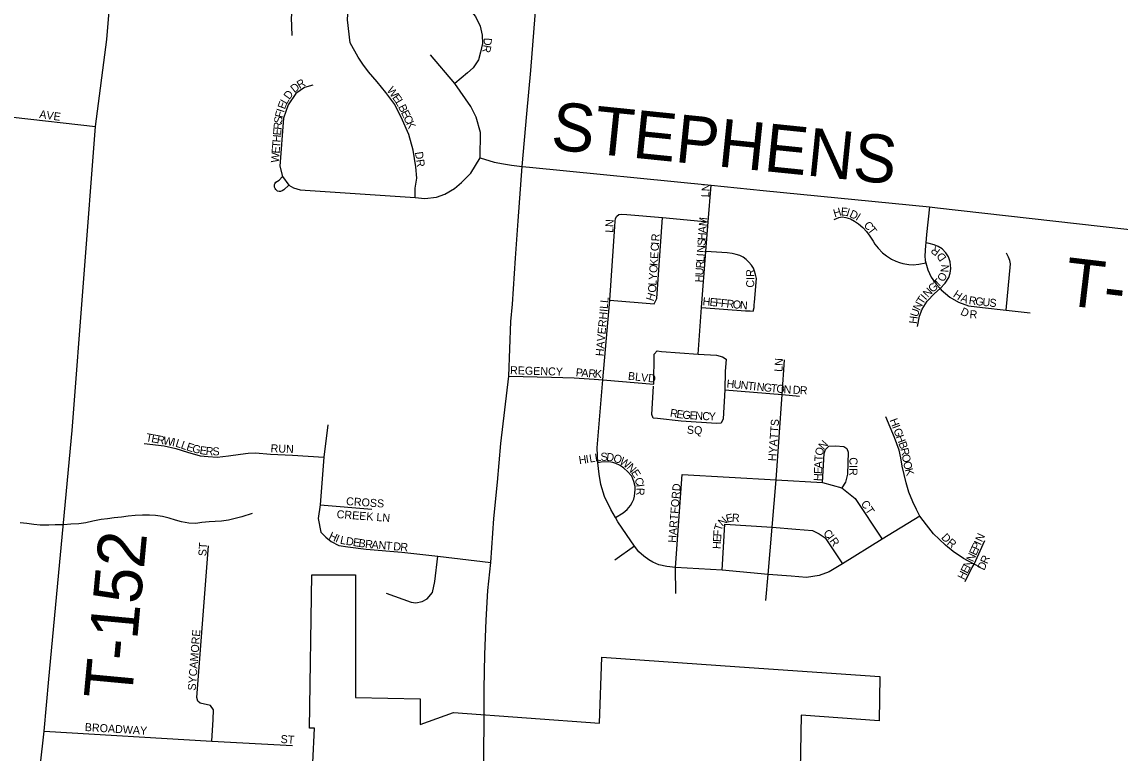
# Model space of a CAD drawing. Extents: x 0 to 1064, y 0 to 440.
# Drawn here: x 220.01 to 240.8, y 110.2 to 124.05 of the extents above; entities that cross this region are included whole.
import ezdxf

# ---------------------------------------------------------------- set-up
doc = ezdxf.new("R2010")
doc.units = 0
for name, color, linetype in [('GM_X_Corporation', 7, 'Continuous'), ('GM_X_Minor_River', 7, 'Continuous'), ('GM_X_State_Route', 7, 'Continuous'), ('GM_X_Township_Road', 7, 'Continuous'), ('GM_X_Township_Road_Text', 7, 'Continuous'), ('GM_X_Township_Subdivision', 7, 'Continuous'), ('GM_X_Township_Subdivision_Text', 7, 'Continuous')]:
    doc.layers.add(name, color=color, linetype=linetype)

msp = doc.modelspace()

# ---------------------------------------------------------------- linework, layer by layer
at = {"layer": 'GM_X_Corporation'}
msp.add_lwpolyline([(225.519, 110.017), (225.548, 110.674), (225.453, 110.674), (225.498, 113.577), (226.325, 113.577), (226.326, 111.25), (227.548, 111.229), (227.548, 110.742), (228.179, 110.967), (230.947, 110.769), (230.991, 112.016), (233.597, 111.834), (236.254, 111.649), (236.239, 110.812), (234.761, 110.916), (234.719, 108.501)], dxfattribs=at)
at = {"layer": 'GM_X_Minor_River'}
msp.add_lwpolyline([(224.371, 114.74), (224.175, 114.677), (224.047, 114.642), (223.925, 114.614), (223.791, 114.592), (223.669, 114.587), (223.554, 114.583), (223.42, 114.567), (223.304, 114.551), (223.17, 114.553), (223.031, 114.579), (222.916, 114.612), (222.801, 114.65), (222.674, 114.682), (222.541, 114.703), (222.425, 114.705), (222.297, 114.707), (222.158, 114.703), (222.024, 114.687), (221.896, 114.67), (221.756, 114.654), (221.634, 114.638), (221.512, 114.622), (221.353, 114.594), (221.219, 114.56), (221.091, 114.544), (220.939, 114.534), (220.805, 114.524), (220.641, 114.52), (220.519, 114.516), (220.355, 114.519), (220.234, 114.527), (220.106, 114.547), (219.979, 114.561)], dxfattribs=at)
at = {"layer": 'GM_X_State_Route'}
for points in [[(228.765, 111.236), (228.765, 111.419), (228.774, 112.064), (228.803, 112.719), (228.831, 113.279), (228.888, 113.811), (228.945, 114.646), (229.017, 115.33), (229.078, 116.067), (229.227, 117.342), (229.266, 118.375), (229.296, 118.706), (229.357, 119.573), (229.406, 120.28), (229.483, 121.311), (229.568, 122.31), (229.646, 123.13), (229.747, 124.412), (229.849, 125.67), (229.956, 126.863), (230.045, 127.996), (230.105, 128.741), (230.16, 129.443)], [(229.373, 105.049), (229.288, 105.381), (229.088, 106.224), (228.942, 106.848), (228.854, 107.296), (228.756, 107.904), (228.743, 108.188), (228.755, 108.559), (228.747, 109.648), (228.764, 110.789), (228.765, 111.236)]]:
    msp.add_lwpolyline(points, dxfattribs=at)
at = {"layer": 'GM_X_Township_Road'}
for points in [[(220.2, 108.53), (220.435, 110.616), (220.518, 111.602), (220.964, 116.308), (221.407, 122.067), (221.618, 123.72), (221.996, 128.334)], [(228.689, 121.476), (228.951, 121.392), (229.127, 121.359), (229.282, 121.336), (229.483, 121.311), (229.623, 121.297)], [(229.623, 121.297), (233.057, 120.957), (234.045, 120.859), (237.191, 120.545), (237.343, 120.53), (241.771, 120.032), (246.092, 119.543), (248.914, 119.184), (250.359, 119.027), (251.284, 118.916)]]:
    msp.add_lwpolyline(points, dxfattribs=at)
at = {"layer": 'GM_X_Township_Subdivision'}
for points in [[(225.126, 123.795), (225.118, 124.135), (225.138, 124.302), (225.15, 124.487), (225.192, 124.642), (225.273, 124.773), (225.38, 124.877), (225.511, 124.934), (225.651, 124.958), (225.821, 124.952), (226.227, 124.916), (227.574, 124.821), (227.863, 124.752), (228.081, 124.636), (228.427, 124.356), (228.597, 124.153), (228.686, 123.971), (228.725, 123.798), (228.734, 123.64), (228.695, 123.476), (228.653, 123.333), (228.552, 123.181), (228.447, 123.087), (228.206, 122.886)], [(227.458, 120.721), (227.458, 120.9), (227.485, 121.091), (227.467, 121.306), (227.416, 121.622), (227.336, 121.917), (227.216, 122.191), (227.07, 122.483), (226.903, 122.716), (226.736, 122.916), (226.572, 123.106), (226.468, 123.25), (226.379, 123.381), (226.227, 123.655), (226.176, 124.087), (226.227, 124.916)], [(225.522, 122.853), (225.358, 122.805), (225.199, 122.693), (225.049, 122.479), (224.964, 122.227), (224.896, 121.316), (224.947, 121.119), (225.066, 120.957), (225.156, 120.907), (225.28, 120.867), (227.458, 120.721), (227.64, 120.704), (227.863, 120.733), (228.018, 120.79), (228.203, 120.897), (228.334, 121.008), (228.507, 121.187), (228.689, 121.476), (228.695, 121.953), (228.609, 122.245), (228.513, 122.445), (228.206, 122.886), (227.747, 123.425)], [(214.327, 122.163), (214.581, 122.128), (214.859, 122.187), (215.096, 122.341), (215.363, 122.43), (215.653, 122.477), (215.955, 122.501), (216.245, 122.537), (216.47, 122.59), (216.772, 122.637), (217.139, 122.643), (218.359, 122.448), (219.847, 122.245), (221.407, 122.067)], [(225.066, 120.957), (224.967, 120.871), (224.939, 120.85), (224.908, 120.84), (224.881, 120.84), (224.852, 120.847), (224.837, 120.857), (224.818, 120.874), (224.804, 120.893), (224.794, 120.917), (224.794, 120.944), (224.794, 120.969), (224.798, 120.985), (224.821, 121.012), (224.881, 121.054), (224.947, 121.119)], [(232.812, 117.759), (232.879, 118.643), (232.96, 119.7), (233.004, 120.266), (233.057, 120.957)], [(237.012, 114.686), (236.3, 114.254), (235.547, 113.782), (235.296, 113.633), (235.107, 113.562), (234.866, 113.528), (234.572, 113.548), (234.138, 113.585), (233.267, 113.665), (232.386, 113.718), (232.219, 113.736), (232.067, 113.765), (231.954, 113.814), (231.878, 113.859), (231.782, 113.93), (231.689, 114.014), (231.606, 114.118), (231.457, 114.338), (231.293, 114.578), (231.247, 114.661), (231.16, 114.812), (231.043, 115.063), (230.968, 115.286), (230.94, 115.48), (230.914, 115.699), (230.9, 115.984), (231.006, 117.268), (231.139, 118.776), (231.235, 120.176), (231.242, 120.273), (231.25, 120.329), (231.271, 120.368), (231.312, 120.399), (231.37, 120.41), (231.462, 120.403), (232.136, 120.348), (233.004, 120.266)], [(237.191, 120.545), (237.138, 120.021), (237.122, 119.863), (237.117, 119.817), (237.105, 119.622), (237.114, 119.531), (237.123, 119.484), (237.161, 119.354), (237.223, 119.212), (237.321, 119.082), (237.393, 118.999), (237.415, 118.973), (237.578, 118.834), (237.743, 118.739), (237.932, 118.674), (238.195, 118.642), (238.645, 118.589), (239.096, 118.536)], [(231.139, 118.776), (231.981, 118.71), (232.03, 118.808), (232.136, 120.348)], [(235.389, 120.309), (235.479, 120.344), (235.541, 120.357), (235.612, 120.348), (235.695, 120.322), (235.776, 120.277), (235.847, 120.225), (235.934, 120.154), (236.002, 120.08), (236.066, 119.99), (236.124, 119.896), (236.16, 119.841), (236.221, 119.767), (236.305, 119.677), (236.379, 119.616), (236.472, 119.558), (236.556, 119.516), (236.627, 119.49), (236.691, 119.471), (236.801, 119.455), (236.885, 119.448), (236.991, 119.458), (237.123, 119.484)], [(236.963, 118.282), (237.003, 118.475), (237.054, 118.609), (237.149, 118.76), (237.287, 118.906), (237.393, 118.999), (237.489, 119.103), (237.556, 119.21), (237.587, 119.293), (237.599, 119.376), (237.583, 119.506), (237.552, 119.597), (237.504, 119.676), (237.433, 119.751), (237.358, 119.798), (237.279, 119.83), (237.188, 119.85), (237.122, 119.863)], [(232.879, 118.643), (233.708, 118.576), (233.8, 118.575), (233.854, 118.571), (233.871, 118.639), (233.876, 118.688), (233.88, 118.743), (233.915, 119.187), (233.902, 119.266), (233.883, 119.326), (233.859, 119.384), (233.824, 119.445), (233.775, 119.501), (233.725, 119.55), (233.667, 119.591), (233.605, 119.623), (233.536, 119.647), (233.455, 119.666), (233.364, 119.675), (232.96, 119.7)], [(238.645, 118.589), (238.729, 119.468), (238.716, 119.529), (238.69, 119.593), (238.651, 119.667)], [(231.972, 117.19), (231.981, 117.759), (232.036, 117.819), (232.119, 117.808), (232.812, 117.759), (233.163, 117.737), (233.274, 117.706), (233.345, 117.661), (233.327, 117.43), (233.318, 117.079), (233.285, 116.533), (233.247, 116.451), (233.158, 116.444), (232.492, 116.484), (232.041, 116.535), (231.959, 116.546), (231.939, 116.615), (231.968, 117.148)], [(234.096, 113.089), (234.138, 113.585), (234.215, 114.479), (234.293, 115.378), (234.405, 116.993), (234.451, 117.65)], [(229.227, 117.342), (230.036, 117.321)], [(230.036, 117.321), (230.468, 117.31), (230.843, 117.281)], [(230.843, 117.281), (231.006, 117.268), (231.972, 117.19)], [(233.318, 117.079), (234.405, 116.993), (234.734, 116.962)], [(225.801, 116.419), (225.725, 115.803), (225.655, 114.902), (225.617, 114.642), (225.67, 114.385), (225.762, 114.287), (225.869, 114.207), (226.011, 114.13), (226.182, 114.104), (226.526, 114.061), (227.206, 114.008), (227.883, 113.929), (228.888, 113.811)], [(238.159, 113.715), (238.037, 113.78), (237.839, 113.887), (237.641, 114.02), (237.495, 114.136), (237.374, 114.252), (237.271, 114.355), (237.138, 114.523), (237.012, 114.686), (236.949, 114.811), (236.876, 114.957), (236.803, 115.142), (236.751, 115.318), (236.713, 115.477), (236.678, 115.632), (236.652, 115.795), (236.618, 115.937), (236.532, 116.177), (236.369, 116.569)], [(222.327, 116.067), (222.704, 116.021), (222.924, 115.971), (223.149, 115.897), (223.388, 115.833), (223.535, 115.815), (223.709, 115.805), (223.925, 115.828), (224.15, 115.86), (224.297, 115.883), (224.435, 115.888), (224.715, 115.86), (225.137, 115.842), (225.725, 115.803)], [(235.166, 115.322), (235.197, 115.877), (235.227, 115.953), (235.288, 116.013), (235.411, 116.018), (235.574, 116.009), (235.63, 115.969), (235.655, 115.902), (235.64, 115.485), (235.604, 115.332), (235.533, 115.225)], [(231.247, 114.661), (231.393, 114.751), (231.472, 114.816), (231.533, 114.891), (231.566, 114.944), (231.593, 115.011), (231.609, 115.067), (231.616, 115.127), (231.619, 115.187), (231.618, 115.247), (231.598, 115.347), (231.555, 115.442), (231.474, 115.536), (231.405, 115.599), (231.34, 115.644), (231.257, 115.684), (231.201, 115.701), (231.12, 115.715), (230.978, 115.71), (230.914, 115.699)], [(232.386, 113.71), (232.386, 113.718), (232.511, 115.479), (234.293, 115.378)], [(234.293, 115.378), (235.166, 115.322), (235.533, 115.225), (235.783, 115.021), (236.3, 114.254)], [(225.655, 114.902), (226.635, 114.822)], [(233.267, 113.665), (233.318, 114.533), (234.215, 114.479), (234.662, 114.443), (234.98, 114.415), (235.105, 114.354), (235.217, 114.275), (235.547, 113.782)], [(237.866, 113.449), (237.931, 113.584), (238.002, 113.715), (238.037, 113.78), (238.24, 114.226)], [(223.607, 110.425), (223.635, 110.836), (223.637, 111.02), (223.583, 111.098), (223.384, 111.142), (223.343, 111.183), (223.32, 111.253), (223.544, 114.124)], [(226.905, 113.228), (227.383, 113.056), (227.471, 113.046), (227.588, 113.069), (227.685, 113.124), (227.786, 113.241), (227.828, 113.45), (227.883, 113.929)], [(231.606, 114.118), (231.233, 113.854)], [(232.392, 113.225), (232.386, 113.71)], [(220.435, 110.616), (223.607, 110.425), (225.134, 110.341)]]:
    msp.add_lwpolyline(points, dxfattribs=at)

# ---------------------------------------------------------------- texts
at = {"layer": 'GM_X_Township_Road_Text'}
for s, rotation, p in [('STEPHENS', 354.1652, (230.007, 121.639)), ('T-158', 353.2238, (239.717, 118.69)), ('T-152', 84.6527, (222.087, 111.19))]:
    msp.add_text(s, height=0.9091, rotation=rotation, dxfattribs=at).set_placement(p)
at = {"layer": 'GM_X_Township_Subdivision_Text'}
for s, height, rotation, p in [('D', 0.152, 266.7632, (228.758, 123.752)), ('R', 0.152, 259.9667, (228.751, 123.624)), ('D', 0.152, 38.1069, (225.169, 122.7)), ('R', 0.152, 29.8352, (225.269, 122.779)), ('D', 0.152, 53.8601, (225.074, 122.568)), ('W', 0.152, 306.2412, (226.913, 122.754)), ('E', 0.152, 305.8426, (227.015, 122.614)), ('E', 0.152, 69.7765, (224.989, 122.385)), ('L', 0.152, 60.0247, (225.023, 122.479)), ('L', 0.152, 300.7482, (227.075, 122.531)), ('B', 0.152, 296.7823, (227.129, 122.441)), ('AVE', 0.1515, 352.1434, (220.334, 122.231)), ('S', 0.152, 83.5934, (224.933, 122.122)), ('F', 0.152, 75.7848, (224.944, 122.222)), ('I', 0.152, 72.6016, (224.97, 122.324)), ('E', 0.152, 296.4184, (227.182, 122.334)), ('C', 0.152, 294.9685, (227.229, 122.24)), ('E', 0.152, 85.4609, (224.916, 121.897)), ('R', 0.152, 85.4723, (224.924, 122.004)), ('K', 0.152, 294.0224, (227.28, 122.132)), ('H', 0.152, 85.4705, (224.905, 121.764)), ('E', 0.152, 85.4609, (224.888, 121.552)), ('T', 0.152, 85.4797, (224.897, 121.658)), ('W', 0.152, 85.4723, (224.875, 121.379)), ('DR', 0.1515, 278.5367, (227.451, 121.581)), ('LN', 0.1515, 86.8215, (233.021, 120.725)), ('H', 0.152, 16.4167, (235.396, 120.348)), ('E', 0.152, 355.2681, (235.509, 120.385)), ('I', 0.152, 343.6524, (235.607, 120.377)), ('D', 0.152, 334.9699, (235.665, 120.361)), ('I', 0.152, 327.6796, (235.782, 120.307)), ('L', 0.152, 89.317, (231.208, 120.056)), ('N', 0.152, 87.1791, (231.209, 120.161)), ('A', 0.152, 85.9957, (232.966, 120.043)), ('M', 0.152, 84.6555, (232.976, 120.175)), ('C', 0.152, 310.0481, (235.938, 120.195)), ('T', 0.152, 307.2087, (236.014, 120.105)), ('R', 0.152, 86.4269, (232.076, 119.89)), ('H', 0.152, 85.9751, (232.957, 119.91)), ('C', 0.152, 86.4282, (232.064, 119.703)), ('I', 0.152, 86.4128, (232.071, 119.823)), ('N', 0.152, 85.9957, (232.94, 119.671)), ('S', 0.152, 86.0003, (232.95, 119.804)), ('R', 0.152, 143.6039, (237.408, 119.727)), ('K', 0.152, 86.4128, (232.046, 119.424)), ('E', 0.152, 86.418, (232.055, 119.557)), ('L', 0.152, 86.0003, (232.928, 119.498)), ('I', 0.152, 85.9736, (232.936, 119.604)), ('D', 0.152, 125.0049, (237.522, 119.58)), ('O', 0.152, 86.4348, (232.038, 119.291)), ('U', 0.152, 85.9957, (232.91, 119.245)), ('R', 0.152, 85.9905, (232.92, 119.378)), ('CIR', 0.1515, 90, (233.874, 119.017)), ('N', 0.152, 85.849, (237.551, 119.301)), ('L', 0.152, 86.4458, (232.023, 119.051)), ('Y', 0.152, 86.4128, (232.03, 119.158)), ('H', 0.152, 85.9969, (232.901, 119.112)), ('T', 0.152, 44.2306, (237.355, 119.007)), ('O', 0.152, 58.0252, (237.456, 119.112)), ('H', 0.152, 71.1711, (231.964, 118.748)), ('O', 0.152, 86.6264, (232.015, 118.918)), ('N', 0.152, 45.5409, (237.161, 118.82)), ('G', 0.152, 42.6501, (237.253, 118.913)), ('H', 0.152, 326.5767, (237.627, 118.853)), ('HAVERHILL', 0.1515, 84.9365, (231.021, 117.712)), ('H', 0.152, 354.4177, (232.892, 118.685)), ('E', 0.152, 354.4283, (233.025, 118.672)), ('F', 0.152, 354.4529, (233.131, 118.662)), ('F', 0.152, 354.4172, (233.237, 118.651)), ('R', 0.152, 354.4339, (233.344, 118.641)), ('O', 0.152, 354.4177, (233.463, 118.629)), ('N', 0.152, 355.4881, (233.599, 118.616)), ('N', 0.152, 63.0244, (237.007, 118.571)), ('T', 0.152, 57.5979, (237.065, 118.686)), ('I', 0.152, 48.3701, (237.119, 118.771)), ('A', 0.152, 339.3783, (237.771, 118.762)), ('R', 0.152, 350.8301, (237.928, 118.707)), ('G', 0.152, 354.0337, (238.055, 118.687)), ('U', 0.152, 354.3047, (238.189, 118.673)), ('S', 0.152, 354.2813, (238.321, 118.659)), ('U', 0.152, 72.1662, (236.968, 118.45)), ('D', 0.152, 333.8357, (237.765, 118.513)), ('R', 0.152, 357.3608, (237.949, 118.438)), ('H', 0.152, 83.3195, (236.954, 118.325)), ('LN', 0.1515, 86.8222, (234.408, 117.418)), ('REGENCY', 0.1515, 358.2653, (229.25, 117.378)), ('P', 0.152, 355.7606, (230.492, 117.338)), ('A', 0.152, 355.7337, (230.598, 117.33)), ('R', 0.152, 355.7476, (230.731, 117.321)), ('K', 0.152, 355.759, (230.851, 117.312)), ('BLVD', 0.1515, 353.8336, (231.479, 117.272)), ('H', 0.152, 354.3068, (233.346, 117.125)), ('U', 0.152, 354.2851, (233.478, 117.112)), ('N', 0.152, 354.3047, (233.611, 117.099)), ('T', 0.152, 354.3084, (233.744, 117.085)), ('I', 0.152, 354.3068, (233.85, 117.075)), ('N', 0.152, 354.2851, (233.916, 117.068)), ('G', 0.152, 354.2927, (234.049, 117.055)), ('T', 0.152, 354.2861, (234.182, 117.042)), ('O', 0.152, 354.7331, (234.289, 117.031)), ('N', 0.152, 356.4123, (234.427, 117.018)), ('D', 0.152, 356.7414, (234.601, 117.008)), ('R', 0.152, 356.7191, (234.734, 117)), ('R', 0.152, 350.2143, (232.272, 116.574)), ('E', 0.152, 351.782, (232.395, 116.553)), ('G', 0.152, 355.4206, (232.511, 116.536)), ('E', 0.152, 356.5066, (232.647, 116.525)), ('N', 0.152, 356.6374, (232.754, 116.519)), ('C', 0.152, 356.6221, (232.887, 116.511)), ('Y', 0.152, 358.5966, (233.012, 116.504)), ('HYATTS', 0.1515, 85.8427, (234.288, 115.725)), ('H', 0.152, 290.7786, (236.436, 116.507)), ('I', 0.152, 290.7957, (236.484, 116.382)), ('T', 0.152, 349.3652, (222.348, 116.111)), ('E', 0.152, 349.3652, (222.453, 116.092)), ('R', 0.152, 349.352, (222.557, 116.072)), ('SQ', 0.1515, 356.8222, (232.597, 116.251)), ('G', 0.152, 290.8017, (236.507, 116.32)), ('H', 0.152, 290.7786, (236.555, 116.195)), ('W', 0.152, 349.3757, (222.676, 116.05)), ('I', 0.152, 349.3589, (222.846, 116.018)), ('L', 0.152, 343.2929, (222.907, 116.007)), ('L', 0.152, 340.7009, (223.008, 115.976)), ('E', 0.152, 342.2783, (223.113, 115.94)), ('G', 0.152, 345.4184, (223.223, 115.905)), ('E', 0.152, 351.1685, (223.368, 115.868)), ('R', 0.152, 355.496, (223.486, 115.85)), ('RUN', 0.1515, 358.0261, (224.717, 115.898)), ('N', 0.152, 49.1142, (235.19, 115.935)), ('B', 0.152, 289.6636, (236.602, 116.071)), ('S', 0.152, 359.5809, (223.618, 115.84)), ('H', 0.152, 8.909, (230.565, 115.671)), ('I', 0.152, 8.8658, (230.697, 115.692)), ('L', 0.152, 8.9159, (230.763, 115.702)), ('L', 0.152, 8.8874, (230.868, 115.719)), ('S', 0.152, 1.5031, (230.968, 115.735)), ('D', 0.152, 353.6043, (231.069, 115.738)), ('O', 0.152, 343.217, (231.195, 115.724)), ('W', 0.152, 326.6364, (231.312, 115.691)), ('T', 0.152, 88.2483, (235.166, 115.724)), ('O', 0.152, 76.8383, (235.168, 115.822)), ('CIR', 0.1515, 270, (235.678, 115.803)), ('R', 0.152, 282.9054, (236.641, 115.963)), ('O', 0.152, 280.127, (236.667, 115.848)), ('N', 0.152, 313.4076, (231.45, 115.601)), ('E', 0.152, 88.2594, (235.158, 115.484)), ('A', 0.152, 88.251, (235.162, 115.59)), ('O', 0.152, 282.778, (236.692, 115.709)), ('K', 0.152, 286.3337, (236.724, 115.569)), ('E', 0.152, 302.6367, (231.537, 115.511)), ('C', 0.152, 286.4457, (231.607, 115.395)), ('H', 0.152, 88.251, (235.154, 115.35)), ('I', 0.152, 276.6588, (231.639, 115.286)), ('R', 0.152, 267.984, (231.647, 115.226)), ('HARTFORD', 0.1515, 85.4257, (232.394, 114.179)), ('CROSS', 0.1515, 356.0966, (226.145, 114.898)), ('CT', 0.1515, 303.6867, (235.887, 114.926)), ('CREEK LN', 0.1515, 355.7938, (225.966, 114.652)), ('T', 0.152, 72.2405, (233.254, 114.398)), ('N', 0.152, 42.3038, (233.275, 114.482)), ('E', 0.152, 12.3671, (233.356, 114.563)), ('R', 0.152, 357.3988, (233.449, 114.585)), ('H', 0.152, 335.86, (225.808, 114.26)), ('I', 0.152, 337.2865, (225.933, 114.204)), ('F', 0.152, 87.2088, (233.251, 114.302)), ('C', 0.152, 315.9274, (235.171, 114.348)), ('I', 0.152, 306.7213, (235.253, 114.269)), ('D', 0.152, 312.9132, (237.405, 114.275)), ('N', 0.152, 65.7687, (238.19, 114.186)), ('ST', 0.1515, 86.1743, (223.501, 113.925)), ('L', 0.152, 348.3693, (226.025, 114.169)), ('D', 0.152, 351.0695, (226.137, 114.146)), ('E', 0.152, 351.3204, (226.27, 114.125)), ('B', 0.152, 351.4586, (226.376, 114.109)), ('R', 0.152, 353.9804, (226.502, 114.09)), ('A', 0.152, 355.3531, (226.625, 114.077)), ('N', 0.152, 355.3756, (226.758, 114.066)), ('T', 0.152, 355.3771, (226.891, 114.056)), ('D', 0.152, 355.3834, (227.037, 114.044)), ('R', 0.152, 355.3815, (227.17, 114.033)), ('H', 0.152, 87.2088, (233.239, 114.062)), ('E', 0.152, 87.2088, (233.246, 114.195)), ('R', 0.152, 305.4417, (235.293, 114.217)), ('R', 0.152, 320.8394, (237.512, 114.162)), ('P', 0.152, 65.7934, (238.119, 114.028)), ('I', 0.152, 65.7623, (238.163, 114.125)), ('N', 0.152, 65.4877, (238.019, 113.809)), ('E', 0.152, 65.7861, (238.075, 113.931)), ('R', 0.152, 66.3681, (238.285, 113.772)), ('E', 0.152, 63.4585, (237.911, 113.588)), ('N', 0.152, 63.9789, (237.959, 113.685)), ('D', 0.152, 65.6248, (238.229, 113.649)), ('H', 0.152, 63.4643, (237.851, 113.469)), ('SYCAMORE', 0.1515, 85.544, (223.301, 111.379)), ('BROADWAY', 0.1515, 356.5126, (221.198, 110.618)), ('ST', 0.1515, 356.4254, (224.905, 110.392))]:
    msp.add_text(s, height=height, rotation=rotation, dxfattribs=at).set_placement(p)

doc.saveas('drawing.dxf')
